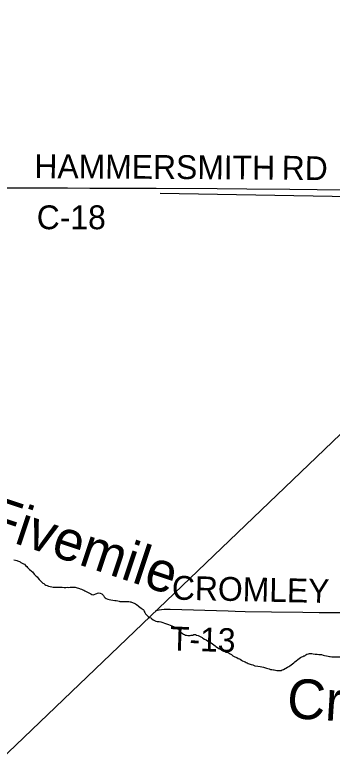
# Model space of a CAD drawing. Extents: x -483 to 680, y 0 to 440.
# Drawn here: x 84 to 121.8, y 160.9 to 248.8 of the extents above; entities that cross this region are included whole.
import ezdxf

# ---------------------------------------------------------------- set-up
doc = ezdxf.new("R2010")
doc.units = 0
for name, color, linetype in [('GM_X_County_Road', 7, 'Continuous'), ('GM_X_County_Road_Text', 7, 'Continuous'), ('GM_X_Minor_River', 7, 'Continuous'), ('GM_X_Minor_River_Text', 7, 'Continuous'), ('GM_X_Township_Road', 7, 'Continuous'), ('GM_X_Township_Road_Text', 7, 'Continuous')]:
    doc.layers.add(name, color=color, linetype=linetype)

msp = doc.modelspace()

# ---------------------------------------------------------------- linework, layer by layer
at = {"layer": 'GM_X_County_Road'}
msp.add_lwpolyline([(76.405, 228.209), (77.732, 228.207), (79.536, 228.205), (81.122, 228.199), (83.017, 228.168), (84.29, 228.169), (85.658, 228.165), (90.256, 228.152), (92.929, 228.14), (100.852, 228.125), (108.125, 228.103), (111.636, 228.062), (116.763, 227.999), (126.559, 227.882)], dxfattribs=at)
at = {"layer": 'GM_X_Minor_River'}
for points in [[(74.642, 128.314), (75.587, 153.634), (193.508, 266.565)], [(101.331, 227.543), (144.59, 226.784)], [(83.883, 183.835), (84.071, 183.771), (84.222, 183.728), (84.317, 183.706), (84.411, 183.665), (84.524, 183.623), (84.617, 183.563), (84.71, 183.503), (84.86, 183.422), (85.01, 183.341), (85.123, 183.299), (85.27, 183.142), (85.399, 183.004), (85.509, 182.887), (85.62, 182.788), (85.731, 182.67), (85.879, 182.551), (85.972, 182.472), (86.084, 182.392), (86.285, 182.119), (86.377, 182.04), (86.45, 181.942), (86.544, 181.882), (86.636, 181.803), (86.746, 181.666), (86.893, 181.49), (86.966, 181.392), (87.132, 181.235), (87.336, 181.038), (87.429, 180.978), (87.578, 180.878), (87.69, 180.817), (87.841, 180.755), (88.01, 180.692), (88.217, 180.628), (88.388, 180.603), (88.559, 180.579), (88.729, 180.554), (88.938, 180.547), (89.148, 180.559), (89.281, 180.555), (89.434, 180.569), (89.643, 180.562), (89.852, 180.536), (90.08, 180.528), (90.271, 180.541), (90.404, 180.537), (90.576, 180.55)], [(90.576, 180.55), (90.729, 180.564), (90.862, 180.559), (91.053, 180.572), (91.186, 180.568), (91.299, 180.526), (91.431, 180.483), (91.563, 180.441), (91.695, 180.418), (91.789, 180.376), (91.921, 180.334), (92.015, 180.293), (92.109, 180.252), (92.221, 180.191), (92.333, 180.111), (92.895, 179.826), (93.065, 179.763), (93.177, 179.703), (93.309, 179.66), (93.462, 179.693), (93.655, 179.763), (93.752, 179.817), (93.847, 179.833), (94.02, 179.865), (94.171, 179.841), (94.34, 179.759), (94.433, 179.68), (94.562, 179.561), (94.653, 179.425), (94.764, 179.307), (94.856, 179.209), (95.063, 179.126), (95.233, 179.083), (95.441, 179.057), (95.668, 179.011), (95.896, 178.985), (96.067, 178.96), (96.256, 178.915), (96.407, 178.891), (96.521, 178.869), (96.635, 178.865), (96.73, 178.862), (96.844, 178.858), (96.996, 178.853), (97.111, 178.868), (97.206, 178.865), (97.301, 178.862), (97.453, 178.857), (97.567, 178.853), (97.719, 178.829), (97.813, 178.807), (97.907, 178.765), (98.02, 178.724), (98.283, 178.601), (98.377, 178.56), (98.488, 178.48), (98.638, 178.38), (98.749, 178.281), (98.898, 178.181), (99.065, 178.061), (99.177, 177.981), (99.269, 177.883), (99.362, 177.804), (99.415, 177.669), (99.487, 177.534), (99.577, 177.397), (99.706, 177.241), (99.872, 177.064), (100.059, 176.963), (100.19, 176.901), (100.338, 176.782), (100.488, 176.682), (100.637, 176.582), (100.787, 176.52), (100.938, 176.477), (101.052, 176.473), (101.204, 176.468), (101.393, 176.424), (101.506, 176.382), (101.638, 176.34), (101.827, 176.276), (102.052, 176.193), (102.297, 176.108), (102.504, 176.025), (102.693, 175.962), (102.786, 175.921), (102.899, 175.879), (103.086, 175.759), (103.255, 175.696), (103.385, 175.597), (103.479, 175.536), (103.57, 175.4), (103.699, 175.282), (103.809, 175.145), (103.977, 175.044), (104.108, 174.964), (104.22, 174.903), (104.352, 174.842), (104.446, 174.819), (104.617, 174.814), (104.884, 174.805)], [(104.884, 174.805), (104.998, 174.82), (105.093, 174.817), (105.19, 174.852), (105.344, 174.904), (105.515, 174.917), (105.647, 174.856), (105.854, 174.792), (106.173, 174.648), (106.323, 174.567), (106.416, 174.488), (106.583, 174.368), (106.79, 174.266), (106.976, 174.146), (107.163, 174.044), (107.388, 173.923), (107.555, 173.784), (107.723, 173.683), (107.853, 173.584), (107.964, 173.485), (108.132, 173.365), (108.318, 173.245), (108.806, 173.019), (108.994, 172.937), (109.2, 172.816), (109.426, 172.751), (109.558, 172.709), (109.651, 172.63), (109.8, 172.53), (109.986, 172.39), (110.21, 172.269), (110.436, 172.166), (110.623, 172.065), (110.754, 172.003), (110.849, 171.981), (111.016, 171.861), (111.147, 171.781), (111.316, 171.699), (111.447, 171.638), (111.56, 171.596), (111.691, 171.535), (111.804, 171.474), (111.917, 171.432), (112.048, 171.39), (112.18, 171.347), (112.369, 171.284), (112.595, 171.2), (112.974, 171.149), (113.22, 171.103), (113.447, 171.058), (113.636, 171.032), (113.749, 170.99), (113.881, 170.948), (113.994, 170.906), (114.145, 170.863), (114.315, 170.819), (114.485, 170.757), (114.617, 170.733), (114.807, 170.708), (114.921, 170.704), (115.053, 170.662), (115.223, 170.637), (115.356, 170.614), (115.47, 170.61), (115.622, 170.605), (115.738, 170.639), (115.873, 170.691), (116.027, 170.744), (116.492, 171.013), (116.647, 171.103), (116.784, 171.194), (116.92, 171.303), (117.095, 171.412), (117.232, 171.521), (117.388, 171.649), (117.545, 171.777), (117.741, 171.942), (117.897, 172.07), (118.034, 172.179), (118.188, 172.25), (118.304, 172.285), (118.458, 172.356), (118.555, 172.39), (118.692, 172.5), (118.808, 172.572), (118.981, 172.623), (119.115, 172.638), (119.249, 172.653), (119.401, 172.647), (119.552, 172.623), (119.779, 172.578), (120.027, 172.57), (120.235, 172.544), (120.388, 172.538), (120.558, 172.514), (120.728, 172.47), (120.917, 172.426), (121.125, 172.381), (121.333, 172.336), (121.485, 172.312), (121.599, 172.308)], [(121.599, 172.308), (121.769, 172.264), (121.883, 172.26), (122.092, 172.234), (122.32, 172.246), (122.511, 172.259), (122.74, 172.27), (122.892, 172.265), (123.062, 172.221), (123.195, 172.198), (123.327, 172.174), (123.459, 172.132), (123.63, 172.107), (124.123, 172.053), (124.237, 172.03), (124.331, 172.008), (124.445, 171.985), (124.558, 171.943), (124.709, 171.9), (124.954, 171.835)]]:
    msp.add_lwpolyline(points, dxfattribs=at)
at = {"layer": 'GM_X_Township_Road'}
msp.add_lwpolyline([(100.737, 177.797), (100.977, 177.829), (101.19, 177.862), (101.458, 177.904), (101.808, 177.936), (102.087, 177.941), (102.522, 177.93), (109.434, 177.72), (110.254, 177.698), (111.466, 177.677), (114.605, 177.627), (118.335, 177.576), (120.262, 177.549), (121.692, 177.538), (123.215, 177.526), (124.516, 177.514), (125.497, 177.506), (127.069, 177.498), (128.397, 177.48), (130.345, 177.458), (131.603, 177.441), (134.027, 177.391), (134.711, 177.379), (137.241, 177.361)], dxfattribs=at)

# ---------------------------------------------------------------- texts
at = {"layer": 'GM_X_County_Road_Text'}
for s, height, rotation, p in [('HAMMERSMITH', 2.84091, 359.63879, (86.313, 229.331)), ('RD', 2.8409, 359.01876, (115.786, 229.162)), ('C-18', 2.8409, 0.00001, (86.599, 223.236))]:
    msp.add_text(s, height=height, rotation=rotation, dxfattribs=at).set_placement(p)
at = {"layer": 'GM_X_Minor_River_Text'}
for s, height, rotation, p in [('Fivemile', 4.7374, 341.5555, (80.112, 187.077)), ('Creek', 4.7372, 356.41895, (116.329, 164.979))]:
    msp.add_text(s, height=height, rotation=rotation, dxfattribs=at).set_placement(p)
at = {"layer": 'GM_X_Township_Road_Text'}
for s, rotation, p in [('CROMLEY', 358.73202, (102.685, 179.081)), ('T-13', 358.23178, (102.447, 173.035))]:
    msp.add_text(s, height=2.8409, rotation=rotation, dxfattribs=at).set_placement(p)

doc.saveas('drawing.dxf')
